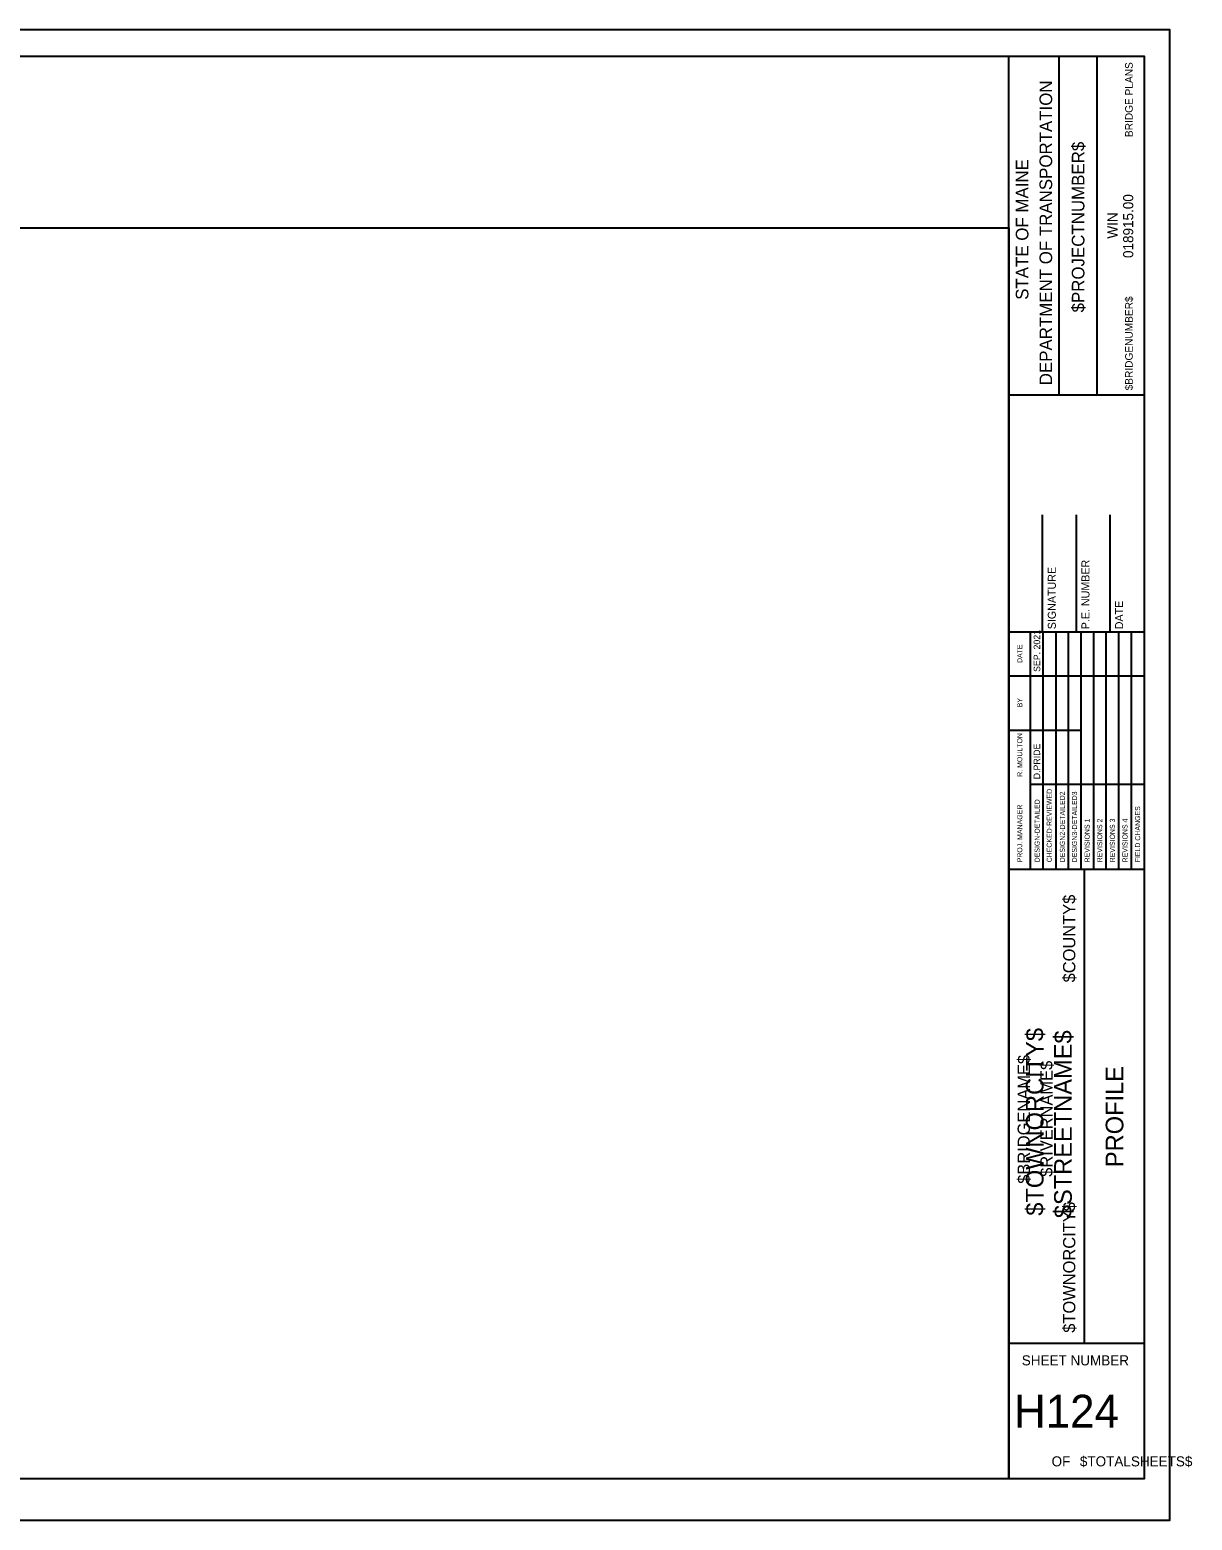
# Model space of a CAD drawing. Extents: x 54039 to 54897, y 9985 to 10535.
# Drawn here: x 54468 to 54897, y 9985 to 10535 of the extents above; entities that cross this region are included whole.
import ezdxf

# ---------------------------------------------------------------- set-up
doc = ezdxf.new("R2010")
doc.units = 0
for name, color, linetype in [('BORDER', 7, 'Continuous'), ('BRIDGE_TITLE', 7, 'Continuous'), ('CLIPS', 7, 'Continuous'), ('HIGHWAY_TITLE', 7, 'Continuous'), ('PLOT BOUNDARY', 7, 'Continuous')]:
    doc.layers.add(name, color=color, linetype=linetype)

msp = doc.modelspace()

# ---------------------------------------------------------------- linework, layer by layer
at = {"layer": 'BORDER'}
for p, q in [((54829.1, 10000), (54829.1, 10525)), ((54847.75, 10399.99), (54847.75, 10524.99)), ((54861.72, 10399.99), (54861.72, 10524.99)), ((54829.11, 10399.97), (54879.1, 10399.97)), ((54841.6, 10312.51), (54841.6, 10355.75)), ((54854.1, 10312.51), (54854.1, 10355.75)), ((54866.6, 10312.51), (54866.6, 10355.75)), ((54829.1, 10312.51), (54879.1, 10312.51)), ((54829.1, 10225.01), (54879.1, 10225.01)), ((54857.06, 10050.01), (54857.06, 10225.01)), ((54829.1, 10050.01), (54879.1, 10050.01))]:
    msp.add_line(p, q, dxfattribs=at)
msp.add_lwpolyline([(54079.1, 10525), (54879.1, 10525), (54879.1, 10000), (54079.1, 10000)], close=True, dxfattribs=at)
for points in [[(54837.18, 10296.26), (54837.18, 10312.51)], [(54841.84, 10225.03), (54841.84, 10312.51)], [(54846.5, 10312.51), (54846.5, 10225.03)], [(54851.16, 10225.03), (54851.16, 10312.51)], [(54855.81, 10225.03), (54855.81, 10312.51)], [(54860.47, 10225.03), (54860.47, 10312.51)], [(54865.13, 10225.03), (54865.13, 10312.51)], [(54869.79, 10225.03), (54869.79, 10312.51)], [(54874.45, 10225.03), (54874.45, 10312.51)], [(54837.18, 10225.03), (54837.18, 10308.98)], [(54829.1, 10296.26), (54879.1, 10296.26)], [(54829.1, 10276.26), (54837.18, 10276.26)], [(54837.18, 10276.26), (54855.81, 10276.26)], [(54837.18, 10256.26), (54879.1, 10256.26)]]:
    msp.add_lwpolyline(points, dxfattribs=at)
at = {"layer": 'CLIPS'}
msp.add_lwpolyline([(54079.06, 10461.58), (54829.1, 10461.58), (54829.1, 10000), (54079.06, 10000)], close=True, dxfattribs=at)
at = {"layer": 'PLOT BOUNDARY'}
msp.add_lwpolyline([(54038.64, 9984.7), (54888.64, 9984.7), (54888.64, 10534.7), (54038.64, 10534.7)], close=True, dxfattribs=at)

# ---------------------------------------------------------------- texts
at = {"layer": 'BORDER'}
for s, height, rotation, p in [('DEPARTMENT OF TRANSPORTATION', 4.6588, 90, (54845.14, 10403.53)), ('$PROJECTNUMBER$', 4.6588, 90, (54857.06, 10430.4)), ('STATE OF MAINE', 4.6588, 90, (54836.38, 10435.06)), ('018915.00', 3.726, 90, (54875.08, 10450.49)), ('WIN', 3.726, 90, (54869.29, 10457.65)), ('SIGNATURE', 2.953, 90, (54846.5, 10313.48)), ('P.E. NUMBER', 2.9528, 90, (54858.91, 10313.48)), ('DATE', 2.953, 90, (54871.31, 10313.48)), ('SEP. 2021', 2.423, 90, (54840.72, 10297.74)), ('DATE', 1.857, 90, (54834.12, 10301.04)), ('BY', 1.857, 90, (54834.12, 10284.69)), ('R. MOULTON', 1.864, 90, (54834.12, 10259.03)), ('D.PRIDE', 2.423, 90, (54840.72, 10258.13)), ('CHECKED-REVIEWED', 1.8637, 90, (54845.01, 10227.46)), ('DESIGN2-DETAILED2', 1.8637, 90, (54849.85, 10227.46)), ('DESIGN3-DETAILED3', 1.8637, 90, (54854.32, 10227.46)), ('PROJ. MANAGER', 1.8637, 90, (54834.12, 10227.46)), ('DESIGN-DETAILED', 1.8637, 90, (54840.54, 10227.46)), ('FIELD CHANGES', 1.8637, 90, (54877.62, 10227.46)), ('REVISIONS 1', 1.8637, 90, (54858.98, 10227.46)), ('REVISIONS 2', 1.8637, 90, (54863.64, 10227.46)), ('REVISIONS 3', 1.8637, 90, (54868.3, 10227.46)), ('REVISIONS 4', 1.8637, 90, (54872.96, 10227.46)), ('PROFILE', 6.521, 90, (54871.43, 10115)), ('SHEET NUMBER', 3.7264, 360, (54833.93, 10041.83)), ('H124', 12.097, 360, (54831.11, 10018.91)), ('OF', 3.726, 360, (54844.94, 10004.56)), ('$TOTALSHEETS$', 3.7264, 360, (54855.38, 10004.56))]:
    msp.add_text(s, height=height, rotation=rotation, dxfattribs=at).set_placement(p)
at = {"layer": 'BRIDGE_TITLE'}
for s, height, p in [('BRIDGE PLANS', 2.795, (54874.89, 10495.12)), ('$BRIDGENUMBER$', 2.795, (54874.89, 10401.65)), ('$COUNTY$', 4.536, (54853.7, 10183.17)), ('$BRIDGENAME$', 4.5358, (54836.93, 10108.86)), ('$RIVERNAME$', 4.5358, (54845.32, 10111.43)), ('$TOWNORCITY$', 4.5358, (54853.7, 10053.88))]:
    msp.add_text(s, height=height, rotation=90, dxfattribs=at).set_placement(p)
at = {"layer": 'HIGHWAY_TITLE'}
for s, p in [('$TOWNORCITY$', (54841.96, 10097.06)), ('$STREETNAME$', (54852.4, 10096.16))]:
    msp.add_text(s, height=6.5214, rotation=90, dxfattribs=at).set_placement(p)

doc.saveas('drawing.dxf')
